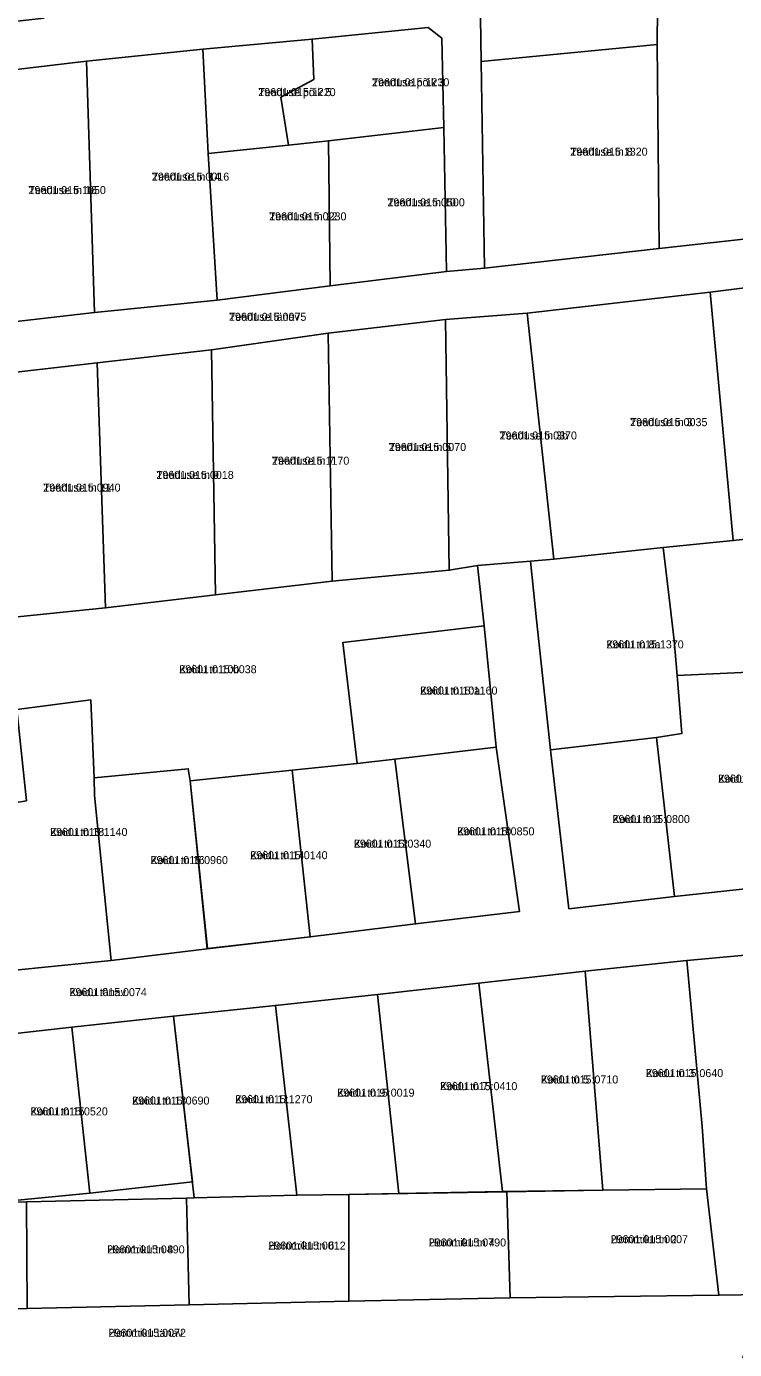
# Model space of a CAD drawing. Extents: x 518839 to 525192, y 6573164 to 6576561.
# Drawn here: x 524409.2 to 524541.9, y 6573866.6 to 6574114.7 of the extents above; entities that cross this region are included whole.
import ezdxf

# ---------------------------------------------------------------- set-up
doc = ezdxf.new("R2010")
doc.units = 0
for name, color, linetype in [('L_AADRESS', 7, 'Continuous'), ('PIIR', 7, 'Continuous'), ('TUNNUS', 7, 'Continuous')]:
    doc.layers.add(name, color=color, linetype=linetype)

msp = doc.modelspace()

# ---------------------------------------------------------------- linework, layer by layer
at = {"layer": 'PIIR'}
for points in [[(524566.74, 6574077.34), (524527.83, 6574073.06), (524527.46, 6574111.26), (524527.62, 6574131.87), (524527.33, 6574152.59), (524541.71, 6574154.3), (524566.75, 6574156.97), (524566.96, 6574123.43)], [(524527.62, 6574131.87), (524527.46, 6574111.26), (524494.48, 6574108.1), (524494.16, 6574128.57)], [(524458.36, 6574092.44), (524456.87, 6574101.4), (524463.08, 6574104.72), (524462.76, 6574112.31), (524484.49, 6574114.46), (524487.07, 6574112.5), (524487.43, 6574095.74), (524465.81, 6574093.22)], [(524442.26, 6574110.41), (524462.76, 6574112.31), (524463.08, 6574104.72), (524456.87, 6574101.4), (524458.36, 6574092.44), (524443.27, 6574090.86)], [(524421.96, 6574061.02), (524420.48, 6574108.17), (524442.26, 6574110.41), (524443.27, 6574090.86), (524444.96, 6574063.33)], [(524494.48, 6574108.1), (524527.46, 6574111.26), (524527.83, 6574073.06), (524495.1, 6574069.37)], [(524420.48, 6574108.17), (524421.96, 6574061.02), (524398.61, 6574058.33), (524397.24, 6574105.44)], [(524487.94, 6574068.74), (524466.12, 6574066.06), (524465.81, 6574093.22), (524487.43, 6574095.74)], [(524443.27, 6574090.86), (524458.36, 6574092.44), (524465.81, 6574093.22), (524466.12, 6574066.06), (524444.96, 6574063.33)], [(524566.9, 6574068.56), (524567.13, 6574021.31), (524563.67, 6574020.69), (524541.67, 6574018.28), (524537.36, 6574064.84)], [(524503.05, 6574060.95), (524537.36, 6574064.84), (524541.67, 6574018.28), (524528.58, 6574017.01), (524508.05, 6574014.82)], [(524487.76, 6574059.73), (524488.47, 6574012.71), (524466.54, 6574010.65), (524465.79, 6574057.2)], [(524503.05, 6574060.95), (524508.05, 6574014.82), (524503.72, 6574014.41), (524493.76, 6574013.6), (524488.47, 6574012.71), (524487.76, 6574059.73)], [(524466.54, 6574010.65), (524444.64, 6574008.11), (524443.93, 6574054.07), (524465.79, 6574057.2)], [(524443.93, 6574054.07), (524444.64, 6574008.11), (524424.01, 6574005.71), (524422.49, 6574051.59)], [(524404.39, 6574003.69), (524400.72, 6574049.09), (524422.49, 6574051.59), (524424.01, 6574005.71), (524405.13, 6574003.76)], [(524528.58, 6574017.01), (524541.67, 6574018.28), (524563.67, 6574020.69), (524565.71, 6573996.13), (524545.93, 6573993.7), (524531.22, 6573992.98), (524530.66, 6573999.56), (524529.89, 6574006)], [(524503.72, 6574014.41), (524508.05, 6574014.82), (524528.58, 6574017.01), (524529.89, 6574006), (524530.66, 6573999.56), (524531.22, 6573992.98), (524532.09, 6573982.1), (524527.34, 6573981.38), (524507.46, 6573979.09), (524504.82, 6574003.46)], [(524405.13, 6574003.76), (524424.01, 6574005.71), (524444.64, 6574008.11), (524466.54, 6574010.65), (524488.47, 6574012.71), (524493.76, 6574013.6), (524495.03, 6574002.32), (524468.55, 6573999.21), (524471.22, 6573976.51), (524459.04, 6573975.23), (524439.93, 6573973.23), (524439.55, 6573975.52), (524421.88, 6573973.78), (524421.27, 6573988.42), (524407.39, 6573986.59)], [(524495.03, 6574002.32), (524497.29, 6573979.57), (524478.25, 6573977.33), (524471.22, 6573976.51), (524468.55, 6573999.21)], [(524531.22, 6573992.98), (524545.93, 6573993.7), (524550.33, 6573953.7), (524530.68, 6573951.57), (524527.34, 6573981.38), (524532.09, 6573982.1)], [(524402.23, 6573968.39), (524409.21, 6573969.52), (524407.39, 6573986.59), (524421.27, 6573988.42), (524421.88, 6573973.78), (524421.96, 6573970.52), (524425.08, 6573939.54), (524405.2, 6573937.58)], [(524507.46, 6573979.09), (524527.34, 6573981.38), (524530.68, 6573951.57), (524510.89, 6573949.28)], [(524478.25, 6573977.33), (524497.29, 6573979.57), (524501.63, 6573948.73), (524482.15, 6573946.44)], [(524421.96, 6573970.52), (524421.88, 6573973.78), (524439.55, 6573975.52), (524439.93, 6573973.23), (524443.07, 6573941.78), (524425.08, 6573939.54)], [(524439.93, 6573973.23), (524459.04, 6573975.23), (524462.4, 6573943.98), (524443.18, 6573941.81)], [(524471.22, 6573976.51), (524478.25, 6573977.33), (524482.15, 6573946.44), (524462.4, 6573943.98), (524459.04, 6573975.23)], [(524533.01, 6573939.58), (524552.12, 6573941.32), (524554.97, 6573910.18), (524547.46, 6573876.94), (524539.01, 6573876.82), (524536.72, 6573896.79), (524535.85, 6573908.44)], [(524513.92, 6573937.59), (524533.01, 6573939.58), (524535.85, 6573908.44), (524536.72, 6573896.79), (524517.25, 6573896.52)], [(524494.04, 6573935.32), (524513.92, 6573937.59), (524517.25, 6573896.52), (524498.45, 6573896.27)], [(524475, 6573933.17), (524479.02, 6573895.88), (524469.65, 6573895.73), (524459.9, 6573895.57), (524455.89, 6573931.16)], [(524475, 6573933.17), (524494.04, 6573935.32), (524498.45, 6573896.27), (524479.02, 6573895.88)], [(524455.89, 6573931.16), (524459.9, 6573895.57), (524440.68, 6573895.1), (524436.78, 6573929.14)], [(524436.78, 6573929.14), (524440.34, 6573898.06), (524421.11, 6573895.96), (524417.7, 6573927.05)], [(524417.7, 6573927.05), (524421.11, 6573895.96), (524402.36, 6573894.13), (524398.81, 6573924.96)], [(524499.27, 6573896.22), (524499.86, 6573876.34), (524469.67, 6573875.71), (524469.65, 6573895.73)], [(524517.25, 6573896.52), (524536.72, 6573896.79), (524539.01, 6573876.82), (524499.86, 6573876.34), (524499.27, 6573896.22)], [(524379.45, 6573891.48), (524383.09, 6573891.9), (524402.36, 6573894.13), (524409.23, 6573894.31), (524409.34, 6573874.31), (524379.68, 6573874.03)], [(524439.22, 6573895.02), (524439.69, 6573875.03), (524409.34, 6573874.31), (524409.23, 6573894.31)], [(524469.65, 6573895.73), (524469.67, 6573875.71), (524439.69, 6573875.03), (524439.22, 6573895.02), (524440.68, 6573895.1), (524459.9, 6573895.57)], [(524307.7, 6573874.1), (524327.15, 6573873.14), (524348.36, 6573872.46), (524379.68, 6573874.03), (524409.34, 6573874.31), (524439.69, 6573875.03), (524469.67, 6573875.71), (524499.86, 6573876.34), (524539.01, 6573876.82), (524547.46, 6573876.94), (524542.18, 6573861.09), (524539.64, 6573864.28), (524508.18, 6573863.78), (524486.83, 6573863.15), (524465.01, 6573862.55), (524443.99, 6573861.97), (524417.49, 6573861.68), (524390.99, 6573861.38), (524377.97, 6573864.01), (524347.85, 6573863.73), (524317.26, 6573863.72), (524305.58, 6573861.99), (524304.04, 6573868.46)]]:
    msp.add_lwpolyline(points, close=True, dxfattribs=at)
for points in [[(524494.16, 6574128.57), (524494.48, 6574108.1), (524495.1, 6574069.37), (524487.94, 6574068.74), (524487.43, 6574095.74), (524487.07, 6574112.5), (524484.49, 6574114.46), (524462.76, 6574112.31), (524442.26, 6574110.41), (524420.48, 6574108.17), (524397.24, 6574105.44), (524373.66, 6574102.67), (524350.74, 6574100.56), (524351.53, 6574052.97), (524344.36, 6574051.79), (524343.39, 6574099.47), (524343.25, 6574108.62), (524361.28, 6574110.35), (524388.38, 6574113.52), (524412.54, 6574116.25)], [(524398.61, 6574058.33), (524421.96, 6574061.02), (524444.96, 6574063.33), (524466.12, 6574066.06), (524487.94, 6574068.74), (524495.1, 6574069.37), (524527.83, 6574073.06), (524566.74, 6574077.34)], [(524566.9, 6574068.56), (524537.36, 6574064.84), (524503.05, 6574060.95), (524487.76, 6574059.73), (524465.79, 6574057.2), (524443.93, 6574054.07), (524422.49, 6574051.59), (524400.72, 6574049.09)], [(524405.2, 6573937.58), (524425.08, 6573939.54), (524443.07, 6573941.78), (524462.4, 6573943.98), (524482.15, 6573946.44), (524501.63, 6573948.73), (524497.29, 6573979.57), (524495.03, 6574002.32), (524493.76, 6574013.6), (524503.72, 6574014.41), (524504.82, 6574003.46), (524507.46, 6573979.09), (524510.89, 6573949.28), (524530.68, 6573951.57), (524550.33, 6573953.7)], [(524552.12, 6573941.32), (524533.01, 6573939.58), (524513.92, 6573937.59), (524494.04, 6573935.32), (524475, 6573933.17), (524455.89, 6573931.16), (524436.78, 6573929.14), (524417.7, 6573927.05), (524398.81, 6573924.96)]]:
    msp.add_lwpolyline(points, dxfattribs=at)

# ---------------------------------------------------------------- texts
at = {"layer": 'L_AADRESS'}
for s, p in [('Teaduse põik 3', (524473.98, 6574103.45)), ('Teaduse põik 5', (524452.67, 6574101.61)), ('Teaduse tn 8', (524511.15, 6574090.44)), ('Teaduse tn 14', (524432.72, 6574085.76)), ('Teaduse tn 16', (524409.6, 6574083.24)), ('Teaduse tn 10', (524476.88, 6574080.95)), ('Teaduse tn 12', (524454.7, 6574078.32)), ('Teaduse tänav', (524447.18, 6574059.49)), ('Teaduse tn 3', (524522.36, 6574039.74)), ('Teaduse tn 3b', (524497.9, 6574037.24)), ('Teaduse tn 5', (524477.13, 6574035.08)), ('Teaduse tn 7', (524455.23, 6574032.51)), ('Teaduse tn 9', (524433.57, 6574029.85)), ('Teaduse tn 11', (524412.36, 6574027.47)), ('Koidu tn 8a', (524517.91, 6573998.08)), ('Koidu tn 10b', (524437.86, 6573993.42)), ('Koidu tn 10a', (524483.01, 6573989.42)), ('Koidu tn 6', (524538.84, 6573972.9)), ('Koidu tn 8', (524519.07, 6573965.33)), ('Koidu tn 18', (524413.65, 6573962.91)), ('Koidu tn 10', (524489.94, 6573963.03)), ('Koidu tn 12', (524470.59, 6573960.72)), ('Koidu tn 16', (524432.48, 6573957.64)), ('Koidu tn 14', (524451.16, 6573958.56)), ('Koidu tänav', (524417.28, 6573932.89)), ('Koidu tn 3', (524525.32, 6573917.71)), ('Koidu tn 7', (524486.73, 6573915.26)), ('Koidu tn 5', (524505.64, 6573916.51)), ('Koidu tn 13', (524429.02, 6573912.56)), ('Koidu tn 11', (524448.34, 6573912.82)), ('Koidu tn 9', (524467.46, 6573914.04)), ('Koidu tn 15', (524409.96, 6573910.53)), ('Hommiku tn 8', (524424.37, 6573884.66)), ('Hommiku tn 6', (524454.55, 6573885.38)), ('Hommiku tn 4', (524484.62, 6573885.96)), ('Hommiku tn 2', (524518.72, 6573886.57)), ('Hommiku tänav', (524424.61, 6573869.02))]:
    msp.add_text(s, height=1.5, dxfattribs=at).set_placement(p)
at = {"layer": 'TUNNUS'}
for s, p in [('29601:015:1230', (524473.98, 6574103.45)), ('29601:015:1220', (524452.67, 6574101.61)), ('29601:015:1320', (524511.15, 6574090.44)), ('29601:015:0016', (524432.72, 6574085.76)), ('29601:015:1050', (524409.6, 6574083.24)), ('29601:015:0500', (524476.88, 6574080.95)), ('29601:015:0230', (524454.7, 6574078.32)), ('29601:015:0075', (524447.18, 6574059.49)), ('29601:015:0035', (524522.36, 6574039.74)), ('29601:015:0370', (524497.9, 6574037.24)), ('29601:015:0070', (524477.13, 6574035.08)), ('29601:015:1170', (524455.23, 6574032.51)), ('29601:015:0018', (524433.57, 6574029.85)), ('29601:015:0940', (524412.36, 6574027.47)), ('29601:015:1370', (524517.91, 6573998.08)), ('29601:015:0038', (524437.86, 6573993.42)), ('29601:015:1160', (524483.01, 6573989.42)), ('29601:015:0048', (524538.84, 6573972.9)), ('29601:015:0800', (524519.07, 6573965.33)), ('29601:015:1140', (524413.65, 6573962.91)), ('29601:015:0850', (524489.94, 6573963.03)), ('29601:015:0340', (524470.59, 6573960.72)), ('29601:015:0960', (524432.48, 6573957.64)), ('29601:015:0140', (524451.16, 6573958.56)), ('29601:015:0074', (524417.28, 6573932.89)), ('29601:015:0640', (524525.32, 6573917.71)), ('29601:015:0410', (524486.73, 6573915.26)), ('29601:015:0710', (524505.64, 6573916.51)), ('29601:015:0690', (524429.02, 6573912.56)), ('29601:015:1270', (524448.34, 6573912.82)), ('29601:015:0019', (524467.46, 6573914.04)), ('29601:015:0520', (524409.96, 6573910.53)), ('29601:015:0490', (524424.37, 6573884.66)), ('29601:015:0012', (524454.55, 6573885.38)), ('29601:015:0790', (524484.62, 6573885.96)), ('29601:015:0007', (524518.72, 6573886.57)), ('29601:015:0072', (524424.61, 6573869.02))]:
    msp.add_text(s, height=1.5, dxfattribs=at).set_placement(p)

doc.saveas('drawing.dxf')
